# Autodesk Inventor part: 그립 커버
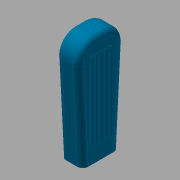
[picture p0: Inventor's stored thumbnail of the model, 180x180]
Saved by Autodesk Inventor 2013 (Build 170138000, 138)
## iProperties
Created: 2017-10
Part Number: 그립 커버
Material: 고무
Document SubType Name: Modeling
Designer: mduedu
Density: 0.93 g/cm^3
Mass: 10.5883 g
Surface Area: 64.0587 cm^2
Volume: 11.3853 cm^3
Author: mduedu
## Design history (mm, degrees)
sketch "스케치1"
  geometry: L1 (0, 7.5)-(50, 7.5); L2 (50, 7.5)-(50, -7.5); L3 (50, -7.5)-(0, -7.5); L4 (0, 10)-(49.477, 12.593); L5 (60, 2.607)-(60, 0); L6 (0, 0)-(60, 0); L7 (60, -2.607)-(60, 0); L8 (0, -10)-(49.477, -12.593); L9 (0, 10)-(0, -10); A1 r 10 centre (50, 2.607) between (60, 2.607) and (49.477, 12.593); A2 r 10 centre (50, -2.607) between (49.477, -12.593) and (60, -2.607); 2 further points
  constraints: 18 end point, 4 point on circle, 4 symmetric about line, 3 point on line, 2 centre point, 2 midpoint, 2 parallel, 2 perpendicular, 2 tangent, 1 coincident, 1 horizontal, 1 other
  dimensions: "d2" = 15 distance of L1.end L2.end; "d3" = 10 radius of A1; "d5" = 10 distance from line of L4.start L6; "d7" = 50 distance between parallel lines of L9 L2; "d8" = 10 distance between parallel lines of L7 L2; "d9" = 93 deg angle of L4 L9
extrude "돌출1" new body sketch "스케치1" stored distance "d10" = 12; taper "d11" = 0 deg
extrude "돌출2" cut sketch "스케치1" stored distance "d12" = 6; taper "d13" = 0 deg
fillet "모깎기1"
fillet "모깎기2" dims "d14" = 0.5
fillet "모깎기3" dims "d15" = 3
sketch "스케치2"
  geometry: L1 (0, 8)-(0, 52); L2 (-6.996, 0)-(6.996, 0) reference; L3 (-2.607, 57)-(2.607, 57) reference; L4 (0, 52)-(-0.5, 52); L5 (-0.5, 52)-(-0.5, 8); L6 (-0.5, 8)-(0, 8); L7 (0, 8)-(0, 52); 2 further points
  constraints: 10 end point, 2 parallel, 1 horizontal, 1 midpoint, 1 perpendicular, 1 vertical, 1 vertical alignment
  dimensions: "d16" = 8 distance from line of L1.start L2; "d17" = 5 distance from line of L1.end L3; "d18" = 0.5 distance of L1.end L4.end
revolve "회전1" sketch "스케치2" stored, may be unused: angle "d19" = 90 deg
fillet "모깎기4" dims "d20" = 0.5
chamfer "모따기1" distance "d27" = 0.5; stored, may be unused: second distance "d28" = 2, angle "d29" = 45 deg
node "솔리드1"
pattern_linear "직사각형 패턴1" dims "d23" = 5, "d26" = -5
mirror "대칭1"
